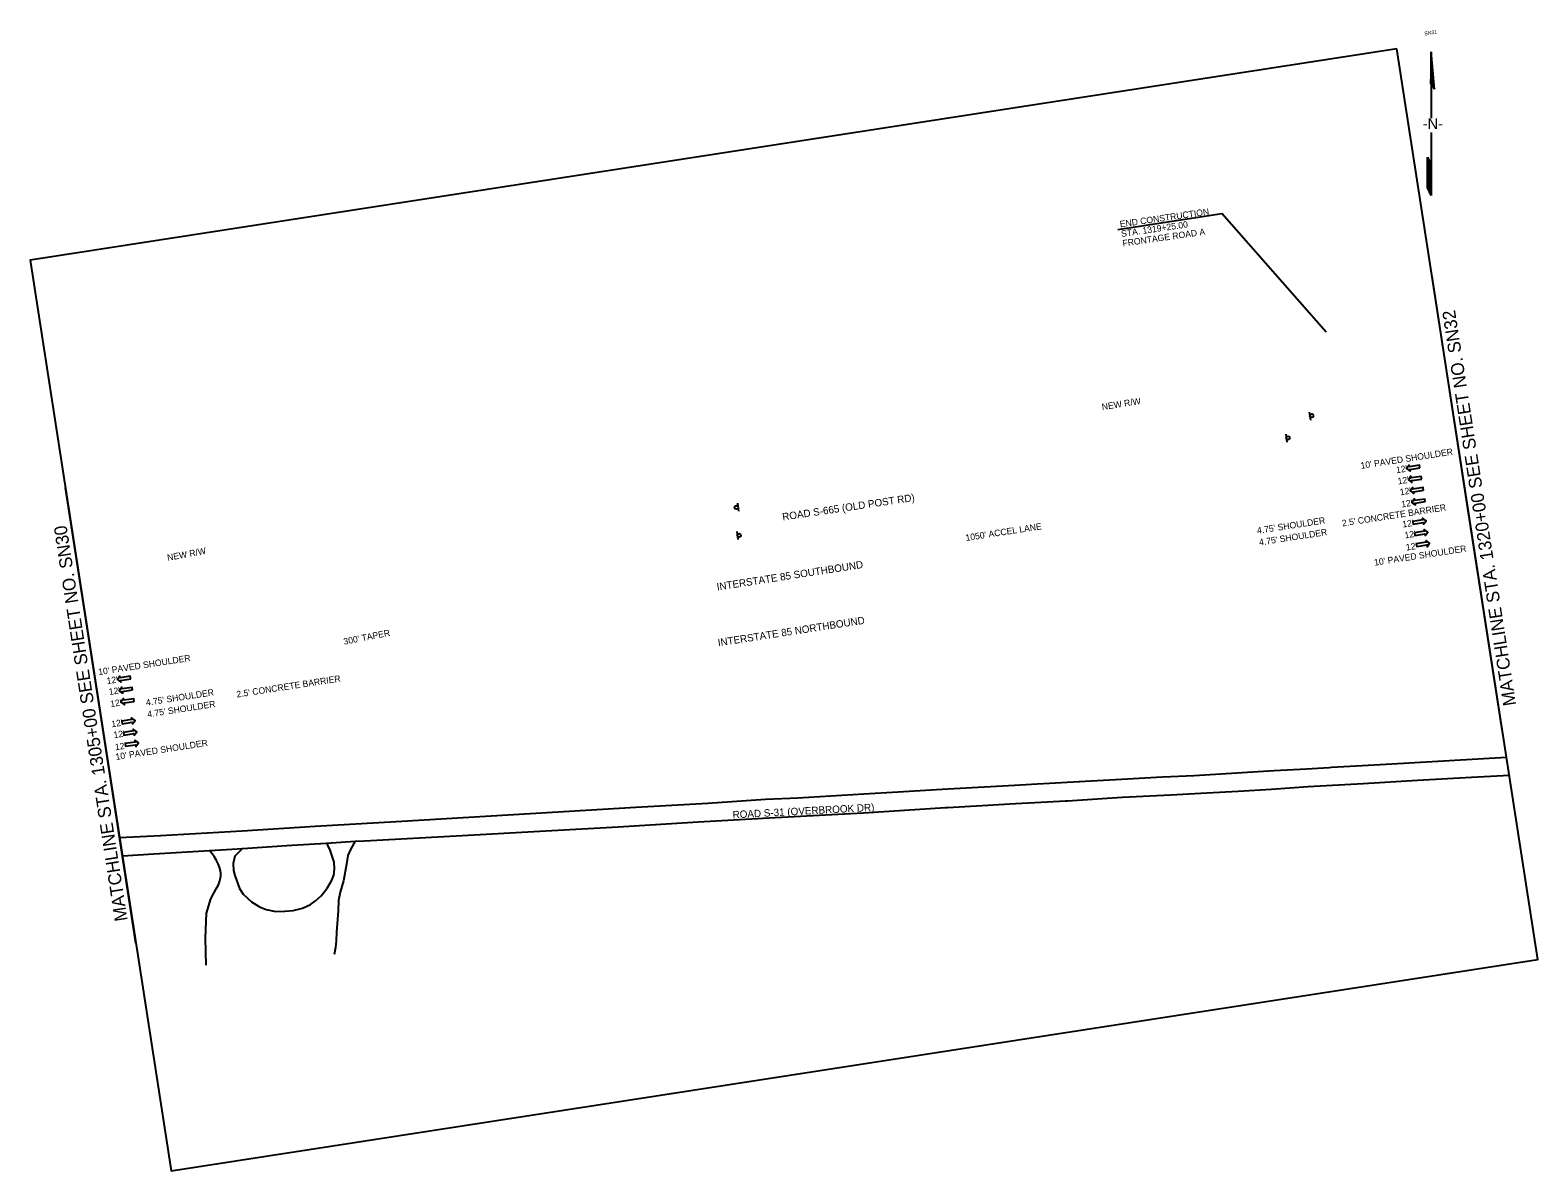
# Model space of a CAD drawing. Extents: x 1779734 to 1781369, y 1180078 to 1181316.
import ezdxf

# ---------------------------------------------------------------- set-up
doc = ezdxf.new("R2010")
doc.units = 0
for name, color, linetype in [('RD_EX_Road', 7, 'Continuous'), ('RD_PD_Final_LnLine', 7, 'Continuous'), ('RD_PD_Final_TX', 7, 'Continuous'), ('RD_PD_RW_TX', 7, 'Continuous'), ('RD_SHT_MatchLine', 7, 'Continuous'), ('RD_SHT_ShtClip', 7, 'Continuous'), ('RD_SHT_TX', 7, 'Continuous'), ('RD_Sketch1', 7, 'Continuous'), ('RD_TX_RoadID', 7, 'Continuous'), ('SN_P_Signs', 7, 'Continuous')]:
    doc.layers.add(name, color=color, linetype=linetype)

# ---------------------------------------------------------------- blocks, each defined once
blk = doc.blocks.new('NA5')
at = {"layer": 'RD_Sketch1'}
for p, q in [((47.5, 65.9), (26.8, 37.4)), ((26.8, 30.6), (47.5, 65.9)), ((27.2, 37.5), (14.5, 19.8)), ((28.1, 38.3), (26.8, 30.6)), ((14.5, 19.8), (5.5, 7.2)), ((-3.5, -5.3), (-18.5, -26.3)), ((-18.5, -26.3), (-43.3, -60.9)), ((-30.6, -36.2), (-22.3, -24.7)), ((-22.3, -24.7), (-24, -34)), ((-41.6, -51.6), (-30.6, -36.2)), ((-43.3, -60.9), (-41.6, -51.6))]:
    blk.add_line(p, q, dxfattribs=at)
for points in [[(27.4, 37.8), (47.4, 65.8)], [(27.1, 37.6), (39.2, 54.5)], [(27.6, 37.9), (46.9, 64.9)], [(27.6, 35.5), (39, 51.5)], [(27.6, 35.3), (38.5, 50.6)], [(27.6, 35.1), (38, 49.7)], [(27.7, 36.2), (40.6, 54.2)], [(27.7, 36), (40.1, 53.3)], [(27.7, 35.8), (39.6, 52.4)], [(27.8, 38.1), (46.4, 64)], [(27.8, 36.8), (42.2, 56.8)], [(27.8, 36.6), (41.7, 56)], [(27.8, 36.4), (41.1, 55.1)], [(27.9, 37.4), (43.8, 59.5)], [(27.9, 37.2), (43.2, 58.6)], [(27.9, 37), (42.7, 57.7)], [(28, 38.1), (45.3, 62.2)], [(28, 37.9), (44.8, 61.3)], [(28, 37.7), (44.3, 60.4)], [(28.1, 38.3), (45.8, 63.1)], [(26.9, 37.5), (29.9, 41.7)], [(26.9, 31.3), (28.5, 33.6)], [(27, 32), (30.1, 36.3)], [(27, 31.8), (29.6, 35.4)], [(27, 31.5), (29.1, 34.5)], [(27.1, 32.6), (31.7, 39)], [(27.1, 32.4), (31.2, 38.1)], [(27.1, 32.2), (30.6, 37.2)], [(27.2, 33.2), (33.3, 41.6)], [(27.2, 33), (32.7, 40.7)], [(27.2, 32.8), (32.2, 39.9)], [(27.3, 33.9), (34.8, 44.3)], [(27.3, 33.7), (34.3, 43.4)], [(27.3, 33.4), (33.8, 42.5)], [(27.4, 34.5), (36.4, 47)], [(27.4, 34.3), (35.9, 46.1)], [(27.4, 34.1), (35.4, 45.2)], [(27.5, 34.9), (37.5, 48.8)], [(27.5, 34.7), (36.9, 47.9)], [(26.8, 30.7), (27, 30.9)], [(26.9, 31.1), (28, 32.7)], [(26.9, 30.9), (27.5, 31.8)], [(-43, -59), (-23.7, -32.1)], [(-43, -59.2), (-23.7, -32.3)], [(-43, -59.4), (-23.8, -32.5)], [(-42.9, -58.6), (-23.6, -31.7)], [(-42.9, -58.8), (-23.7, -31.9)], [(-42.8, -58.1), (-23.5, -31.2)], [(-42.8, -58.3), (-23.6, -31.4)], [(-42.7, -57.5), (-23.4, -30.6)], [(-42.7, -57.7), (-23.5, -30.8)], [(-42.7, -57.9), (-23.5, -31)], [(-42.6, -57), (-23.3, -30.1)], [(-42.6, -57.2), (-23.4, -30.4)], [(-42.5, -56.4), (-23.2, -29.5)], [(-42.5, -56.6), (-23.2, -29.7)], [(-42.5, -56.8), (-23.3, -29.9)], [(-42.4, -55.9), (-23.1, -29)], [(-42.4, -56.1), (-23.2, -29.3)], [(-42.3, -55.3), (-23, -28.4)], [(-42.3, -55.5), (-23, -28.6)], [(-42.3, -55.7), (-23.1, -28.8)], [(-42.2, -54.8), (-22.9, -27.9)], [(-42.2, -55), (-23, -28.2)], [(-42.1, -54.4), (-22.8, -27.5)], [(-42.1, -54.6), (-22.9, -27.7)], [(-42, -53.7), (-22.7, -26.8)], [(-42, -53.9), (-22.7, -27.1)], [(-42, -54.2), (-22.8, -27.3)], [(-41.9, -53.3), (-22.6, -26.4)], [(-41.9, -53.5), (-22.7, -26.6)], [(-41.8, -52.6), (-22.5, -25.7)], [(-41.8, -52.8), (-22.5, -26)], [(-41.8, -53.1), (-22.6, -26.2)], [(-41.7, -52.2), (-22.4, -25.3)], [(-41.7, -52.4), (-22.5, -25.5)], [(-41.6, -51.7), (-22.3, -24.9)], [(-41.6, -52), (-22.4, -25.1)], [(-43.3, -60.8), (-24, -33.9)], [(-43.2, -60.1), (-23.9, -33.2)], [(-43.2, -60.3), (-23.9, -33.4)], [(-43.2, -60.5), (-24, -33.6)], [(-43.1, -59.7), (-23.8, -32.8)], [(-43.1, -59.9), (-23.9, -33)]]:
    blk.add_lwpolyline(points, dxfattribs=at)
blk.add_text('-N-', height=11.81, rotation=324.3865, dxfattribs=at).set_placement((-8.8, 3))
blk = doc.blocks.new('SARRW2')
at = {"layer": 'RD_PD_Final_LnLine'}
blk.add_lwpolyline([(-12, 1.2), (-12, -1.2), (-2.8, -1.2), (-2.8, -2.8), (0, 0), (-2.8, 2.8), (-2.8, 1.2)], close=True, dxfattribs=at)

msp = doc.modelspace()

# ---------------------------------------------------------------- linework, layer by layer
at = {"layer": 'RD_EX_Road'}
for points in [[(1781335.1, 1180527), (1781204.5, 1180519.5), (1781184.8, 1180518.4), (1781145.1, 1180516.1), (1781142.5, 1180516), (1781118.2, 1180514.5), (1781083.1, 1180512.7), (1781019.3, 1180508.7), (1780996.2, 1180507.3), (1780962, 1180505.9), (1780917.5, 1180503.3), (1780871.6, 1180500.8), (1780871.4, 1180500.7), (1780839.2, 1180498.9), (1780826.1, 1180498.1), (1780807.9, 1180497.2), (1780723, 1180492.5), (1780668.9, 1180489.2), (1780644, 1180487.7), (1780638, 1180487.4), (1780566.5, 1180483), (1780531.4, 1180481.4), (1780468.6, 1180477.3), (1780390.8, 1180472.7), (1780300.4, 1180467.4), (1780209.4, 1180462), (1780130.8, 1180457.3), (1780042.7, 1180452.3), (1779963.5, 1180447.3), (1779875.2, 1180442.2), (1779830.7, 1180439.9)], [(1779833.7, 1180420.5), (1779867.7, 1180422.5), (1779928.1, 1180426.2), (1779946.6, 1180427.3), (1779964.1, 1180428.5), (1780017.7, 1180432.1), (1780055.1, 1180434.2), (1780086.3, 1180436.1), (1780096.5, 1180436.7), (1780202.2, 1180442.6), (1780286.5, 1180447.2), (1780371.3, 1180452), (1780458.3, 1180457.4), (1780541.9, 1180462.1), (1780637.5, 1180467.2), (1780726.5, 1180472.8), (1780728.6, 1180472.9), (1780766.4, 1180475.1), (1780802.4, 1180477.1), (1780823.5, 1180478.3), (1780856.6, 1180480.1), (1780858.7, 1180480.2), (1780918.1, 1180484.1), (1780971.1, 1180486.7), (1781010, 1180488.8), (1781043.9, 1180490.7), (1781080, 1180492.6), (1781120, 1180495.6), (1781179.4, 1180498.8), (1781238.5, 1180502.6), (1781296.9, 1180505.7), (1781338.1, 1180508)], [(1779964.1, 1180428.5), (1779955.7, 1180419.9), (1779953.8, 1180412.2), (1779954.4, 1180404.6), (1779955.8, 1180398.9), (1779960.9, 1180384.8), (1779964.8, 1180378.8), (1779973.8, 1180370.6), (1779982.5, 1180364.9), (1779989.5, 1180362.2), (1780000.1, 1180360), (1780009.9, 1180360.2), (1780019, 1180361.1), (1780029.1, 1180363.4), (1780037.8, 1180367.4), (1780043.2, 1180371.4), (1780049.5, 1180377.1), (1780055.7, 1180385.2), (1780060.8, 1180394), (1780063, 1180399.4), (1780063.7, 1180406.4), (1780063.6, 1180413.6), (1780061.8, 1180418.9), (1780059.1, 1180426.4), (1780056.6, 1180431.9), (1780055.1, 1180434.2)], [(1780086.3, 1180436.1), (1780081.4, 1180428), (1780078.2, 1180420.6), (1780076.8, 1180411.2), (1780073.6, 1180393.3), (1780070.1, 1180380.8), (1780068.3, 1180371.9), (1780067.8, 1180360.8), (1780065.8, 1180337.5), (1780065.6, 1180328.1), (1780064.8, 1180320.9), (1780063.4, 1180313.4)], [(1779924.7, 1180301.6), (1779923.7, 1180331.1), (1779925, 1180358.1), (1779929.7, 1180373.8), (1779932.9, 1180379.7), (1779935.4, 1180384.4), (1779937.9, 1180388.8), (1779939.4, 1180393.1), (1779940.4, 1180398.2), (1779940.6, 1180401.4), (1779940.1, 1180404.2), (1779938.9, 1180408.1), (1779937.6, 1180411.8), (1779935.4, 1180416.2), (1779933.1, 1180419.6), (1779931.1, 1180422.4), (1779928.1, 1180426.2)]]:
    msp.add_lwpolyline(points, dxfattribs=at)
at = {"layer": 'RD_PD_Final_TX'}
for p in [(1780913.5, 1181100.2), (1781139.4, 1180988.8)]:
    msp.add_line(p, (1781026.4, 1181117.6), dxfattribs=at)
at = {"layer": 'RD_SHT_MatchLine'}
for points in [[(1781330.8, 1180555), (1781292.5, 1180802), (1781254.3, 1181049.1)], [(1779848.4, 1180325.5), (1779810.2, 1180572.6), (1779771.9, 1180819.6)]]:
    msp.add_lwpolyline(points, dxfattribs=at)
at = {"layer": 'RD_SHT_ShtClip'}
msp.add_lwpolyline([(1781216, 1181296.2), (1779733.7, 1181066.7), (1779886.7, 1180078.5), (1781369, 1180307.9)], close=True, dxfattribs=at)
at = {"layer": 'SN_P_Signs'}
for p, q in [((1781120.8, 1180902), (1781122.6, 1180893.2)), ((1781095.5, 1180878.1), (1781096.6, 1180869.2)), ((1780502.5, 1180794.3), (1780501.1, 1180803.2)), ((1780500.1, 1180772.5), (1780501.2, 1180763.5))]:
    msp.add_line(p, q, dxfattribs=at)
for centre in [(1781123.7, 1180898), (1781098, 1180873.9), (1780499.8, 1180798.5), (1780502.6, 1180768.2)]:
    msp.add_circle(centre, 2, dxfattribs=at)

# ---------------------------------------------------------------- block references
at = {"layer": 'RD_PD_Final_LnLine', "xscale": 1.2}
for p, yscale, rotation in [((1781226.7, 1180840.6), 1.2, -171.19998882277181), ((1781228.6, 1180828.5), 1.2, -171.19998882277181), ((1781230.5, 1180816.4), 1.2, -171.19998882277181), ((1781232.4, 1180804), 1.2, -171.19998882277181), ((1781247.8, 1180784.1), 1.1999999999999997, 8.800011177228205), ((1781249.7, 1180771.7), 1.1999999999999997, 8.800011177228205), ((1781251.6, 1180759.7), 1.1999999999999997, 8.800011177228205), ((1779828.3, 1180611.7), 1.2, -171.19998882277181), ((1779830.2, 1180599.6), 1.2, -171.19998882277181), ((1779832.1, 1180587.2), 1.2, -171.19998882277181), ((1779847.5, 1180567.3), 1.1999999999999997, 8.800011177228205), ((1779849.4, 1180555), 1.1999999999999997, 8.800011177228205), ((1779851.2, 1180542.9), 1.1999999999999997, 8.800011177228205)]:
    msp.add_blockref('SARRW2', p, dxfattribs=dict(at, yscale=yscale, rotation=rotation))
at = {"layer": 'RD_SHT_MatchLine', "rotation": 35.61349782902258}
msp.add_blockref('NA5', (1781253, 1181211.8), dxfattribs=at)

# ---------------------------------------------------------------- texts
at = {"layer": 'RD_PD_Final_TX'}
for s, rotation, p in [('END CONSTRUCTION', 8.1732, (1780916.1, 1181102.4)), ('STA. 1319+25.00', 8.1732, (1780917.5, 1181092)), ('FRONTAGE ROAD A', 8.1732, (1780919, 1181081.6)), ("10' PAVED SHOULDER", 8.8, (1781177.3, 1180840.3)), ("12'", 8.8, (1781215.7, 1180835.5)), ("12'", 8.8, (1781217.5, 1180823.4)), ("12'", 8.8, (1781219.9, 1180811.6)), ("12'", 8.8, (1781221.4, 1180798.4)), ("2.5' CONCRETE BARRIER", 8.8, (1781157.1, 1180777.8)), ("1050' ACCEL LANE", 8.8, (1780748.8, 1180762)), ("4.75' SHOULDER", 8.8, (1781065, 1180769.8)), ("4.75' SHOULDER", 8.8, (1781067.2, 1180757.1)), ("12'", 8.8, (1781222.6, 1180776.6)), ("12'", 8.8, (1781225, 1180764.8)), ("10' PAVED SHOULDER", 8.8, (1781192, 1180735.2)), ("12'", 8.8, (1781226.5, 1180751.6)), ("300' TAPER", 11.0906, (1780074.3, 1180649.4)), ("10' PAVED SHOULDER", 8.8, (1779808.1, 1180616.4)), ("12'", 8.8, (1779817.2, 1180606.6)), ("2.5' CONCRETE BARRIER", 8.8, (1779958, 1180592.1)), ("12'", 8.8, (1779819.6, 1180594.8)), ("4.75' SHOULDER", 8.8, (1779859.7, 1180583.2)), ("12'", 8.8, (1779821.1, 1180581.7)), ("4.75' SHOULDER", 8.8, (1779861.3, 1180570.5)), ("12'", 8.8, (1779822.3, 1180559.8)), ("12'", 8.8, (1779824.7, 1180548)), ("10' PAVED SHOULDER", 8.8, (1779826.8, 1180524.3)), ("12'", 8.8, (1779826.2, 1180534.8))]:
    msp.add_text(s, height=7, rotation=rotation, dxfattribs=at).set_placement(p)
at = {"layer": 'RD_PD_RW_TX'}
for rotation, p in [(8.9527, (1780896.6, 1180904.1)), (10.5528, (1779883, 1180740.4))]:
    msp.add_text('NEW R/W', height=7, rotation=rotation, dxfattribs=at).set_placement(p)
at = {"layer": 'RD_SHT_MatchLine'}
for s, p in [('MATCHLINE STA. 1320+00 SEE SHEET NO. SN32', (1781345.5, 1180584.2)), ('MATCHLINE STA. 1305+00 SEE SHEET NO. SN30', (1779839.5, 1180350.4))]:
    msp.add_text(s, height=14, rotation=98.8, dxfattribs=at).set_placement(p)
at = {"layer": 'RD_SHT_TX'}
msp.add_text('SN31', height=4, rotation=8.8, dxfattribs=at).set_placement((1781246.4, 1181310.7))
at = {"layer": 'RD_TX_RoadID'}
for s, rotation, p in [('ROAD S-665 (OLD POST RD)', 8.4657, (1780550.1, 1180784.2)), ('INTERSTATE 85 SOUTHBOUND', 8.8, (1780479, 1180708.3)), ('INTERSTATE 85 NORTHBOUND', 8.8, (1780480.2, 1180647.7)), ('ROAD S-31 (OVERBROOK DR)', 3.0316, (1780495.8, 1180461))]:
    msp.add_text(s, height=8, rotation=rotation, dxfattribs=at).set_placement(p)

doc.saveas('drawing.dxf')
